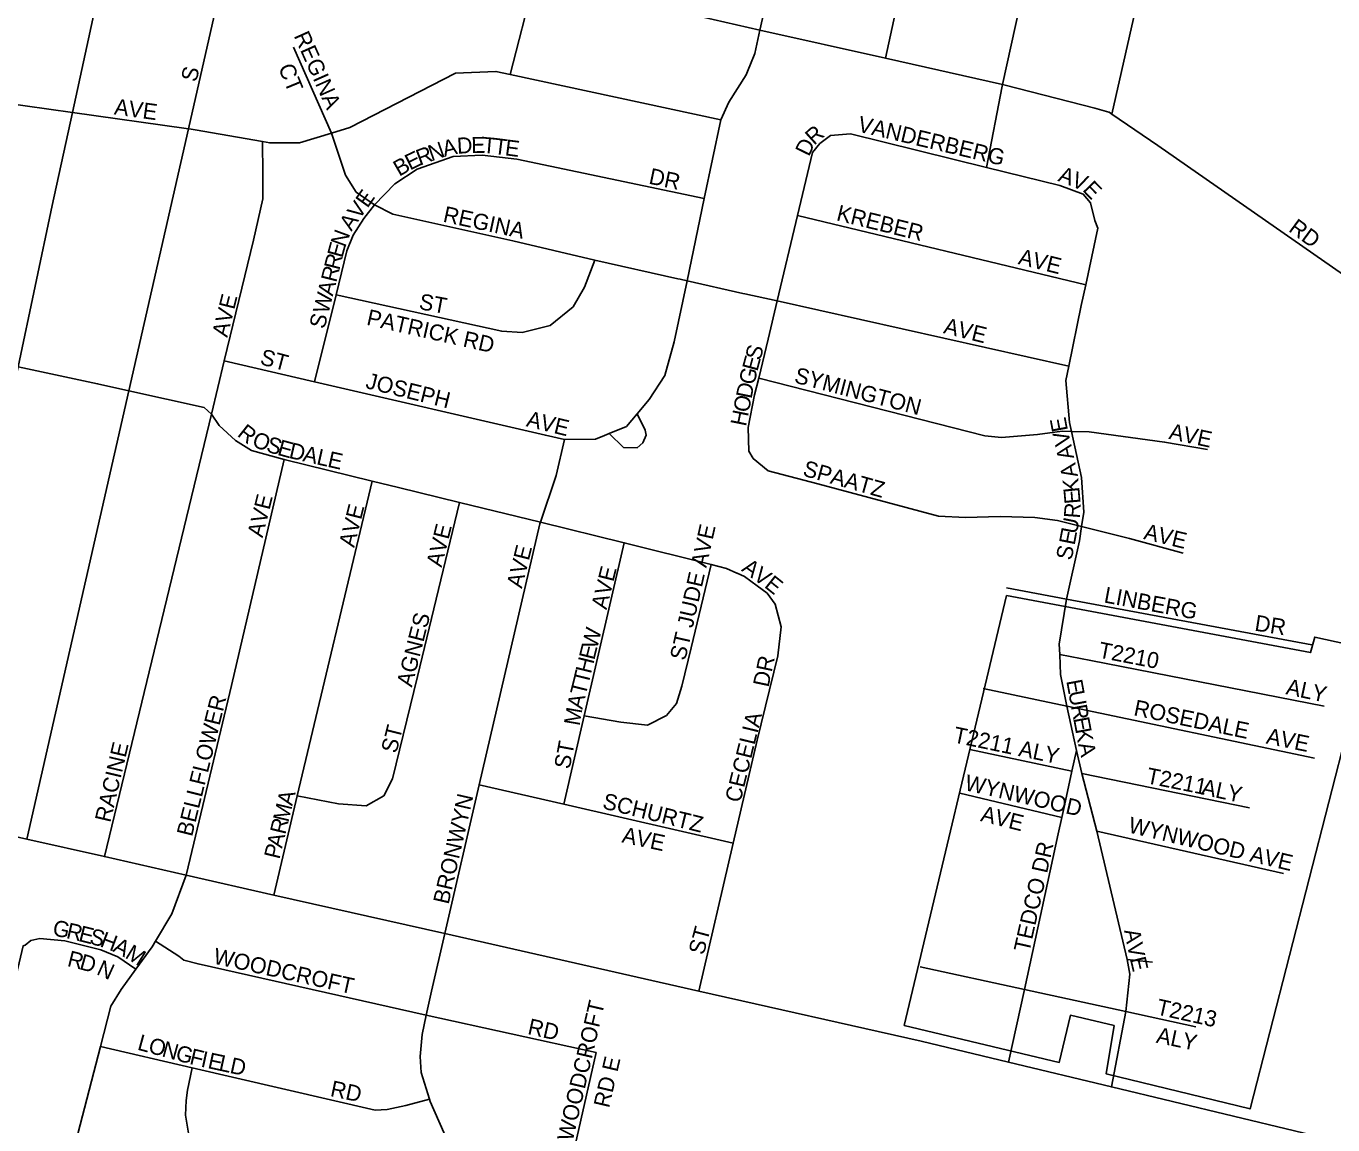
# Model space of a CAD drawing. Extents: x 0 to 34, y -6.2 to 22.
# Drawn here: x 2.696 to 3.469, y 15.73 to 16.379 of the extents above; entities that cross this region are included whole.
import ezdxf

# ---------------------------------------------------------------- set-up
doc = ezdxf.new("R2010")
doc.units = 0
for name, color, linetype in [('GM_X_City_Street', 7, 'Continuous'), ('GM_X_City_Street_Text', 7, 'Continuous'), ('GM_X_Corporation', 7, 'Continuous'), ('GM_X_Township_Subdivision', 7, 'Continuous'), ('GM_X_Township_Subdivision_Text', 7, 'Continuous')]:
    doc.layers.add(name, color=color, linetype=linetype)

msp = doc.modelspace()

# ---------------------------------------------------------------- linework, layer by layer
at = {"layer": 'GM_X_City_Street'}
for points in [[(3.27368, 16.34478), (3.29673, 16.4497), (3.30954, 16.50801), (3.315, 16.53353), (3.31528, 16.53481), (3.32593, 16.58379), (3.32697, 16.59444), (3.32648, 16.60621), (3.3225, 16.6267), (3.32074, 16.63388), (3.29313, 16.7464), (3.25795, 16.89783), (3.24882, 17.00989), (3.23911, 17.16213), (3.23906, 17.16288), (3.23518, 17.3149), (3.22829, 17.42881), (3.22212, 17.56473), (3.2207, 17.60083)], [(3.12582, 16.35982), (3.12602, 16.36031), (3.12718, 16.36323), (3.1303, 16.37705), (3.15398, 16.48197), (3.17382, 16.56986), (3.17844, 16.59036), (3.18149, 16.60756), (3.18168, 16.61593), (3.15792, 16.7142), (3.1215, 16.86577), (3.11952, 16.89635), (3.11304, 17.00234), (3.1055, 17.15726), (3.09863, 17.29851), (3.09286, 17.41697), (3.08623, 17.55807), (3.08431, 17.59258)], [(3.33825, 16.32736), (3.36258, 16.4344), (3.3817, 16.51834), (3.3921, 16.56843), (3.3939, 16.5791), (3.39226, 16.59276), (3.38446, 16.61625), (3.37857, 16.63785), (3.37644, 16.64731), (3.35105, 16.76018), (3.33506, 16.83126), (3.31648, 16.91147), (3.3102, 16.97771), (3.30815, 17.01318), (3.30664, 17.03928), (3.30004, 17.15352), (3.29942, 17.16433), (3.29682, 17.28631)], [(3.20453, 16.36034), (3.22737, 16.4658), (3.24604, 16.55197), (3.25332, 16.58561), (3.25573, 16.60645), (3.25505, 16.61804), (3.25493, 16.62015), (3.22734, 16.73073), (3.19762, 16.84785), (3.18989, 16.88188), (3.1871, 16.92348), (3.18183, 17.00616), (3.17392, 17.15656), (3.17386, 17.15779)], [(2.98264, 16.35074), (2.9967, 16.4053), (2.99695, 16.40657), (2.99976, 16.42157), (3.01237, 16.51308), (3.02837, 16.62912), (3.02846, 16.63274), (3.02872, 16.64356), (3.02719, 16.65842), (3.01097, 16.72809), (2.99061, 16.8133)], [(2.66856, 16.07037), (2.66859, 16.07053), (2.6758, 16.10297), (2.6917, 16.1781), (2.71187, 16.27344), (2.72379, 16.32828), (2.75181, 16.45725), (2.7729, 16.55191)], [(2.82035, 16.4436), (2.82079, 16.44351), (2.82087, 16.4435), (2.87661, 16.43239), (2.90811, 16.42612), (2.93022, 16.42125), (2.99695, 16.40657), (3.05998, 16.39095), (3.09568, 16.38484), (3.1303, 16.37705), (3.20453, 16.36034), (3.27368, 16.34478), (3.27531, 16.34441), (3.32823, 16.33089), (3.33654, 16.32852), (3.33666, 16.32844)], [(2.69685, 15.899), (2.75714, 16.16389), (2.79237, 16.31868), (2.81947, 16.43771), (2.81948, 16.43774)], [(2.87706, 16.31616), (2.85447, 16.36698)], [(2.4876, 16.36137), (2.48773, 16.36135), (2.55231, 16.3523), (2.60686, 16.34467), (2.66762, 16.33615), (2.72379, 16.32828), (2.79099, 16.31887), (2.79237, 16.31868), (2.79396, 16.31845), (2.79646, 16.31802)], [(3.05143, 16.14278), (3.05778, 16.15035), (3.06477, 16.15868), (3.07396, 16.17296), (3.07961, 16.19287), (3.08716, 16.22884), (3.09736, 16.27743), (3.10713, 16.32398), (3.11185, 16.33436), (3.12214, 16.35057), (3.12582, 16.35982)], [(2.79646, 16.31802), (2.83612, 16.31114), (2.84052, 16.31037), (2.85801, 16.31039), (2.87706, 16.31616), (2.88785, 16.31943), (2.95026, 16.35165), (2.97418, 16.35256), (2.98264, 16.35074), (3.10713, 16.32398)], [(3.26422, 16.29587), (3.2735, 16.34382), (3.27368, 16.34478)], [(3.33666, 16.32844), (3.33825, 16.32736), (3.36551, 16.30882), (3.54342, 16.18487), (3.64626, 16.1082), (3.6811, 16.09043), (3.69827, 16.08429), (3.73179, 16.07547), (3.74914, 16.07149), (3.76801, 16.06713)], [(2.74276, 15.8886), (2.80597, 16.15013), (2.81359, 16.18165), (2.83079, 16.25279), (2.83633, 16.27735), (2.8363, 16.29179), (2.83612, 16.31114)], [(2.87706, 16.31616), (2.88529, 16.29135), (2.8915, 16.28132), (2.90234, 16.27384), (2.91322, 16.26825), (2.98424, 16.25245), (3.03258, 16.241), (3.08172, 16.23005), (3.08309, 16.22974)], [(3.12621, 16.12394), (3.12365, 16.12818), (3.12324, 16.14226), (3.12713, 16.16154), (3.12953, 16.17139), (3.13514, 16.19441), (3.14051, 16.21694), (3.15251, 16.26741), (3.16139, 16.30473), (3.16569, 16.30995), (3.17197, 16.31479)], [(3.17197, 16.31479), (3.18374, 16.31581), (3.26422, 16.29587), (3.30761, 16.28512), (3.32141, 16.28011), (3.32571, 16.27487)], [(2.90234, 16.27384), (2.91441, 16.28608), (2.92754, 16.29488), (2.94899, 16.30233), (2.9661, 16.30306), (2.98656, 16.30066), (3.09736, 16.27743)], [(2.86702, 16.16925), (2.87969, 16.22057), (2.88609, 16.24649), (2.88974, 16.2559), (2.89606, 16.26563), (2.90234, 16.27384)], [(3.31161, 16.04084), (3.31913, 16.07513), (3.32048, 16.08368), (3.32182, 16.09217), (3.32042, 16.11272), (3.31442, 16.13985), (3.31323, 16.1452), (3.31118, 16.16995), (3.31293, 16.17851), (3.32024, 16.21419), (3.32289, 16.22651), (3.33009, 16.25994), (3.3283, 16.26454), (3.32571, 16.27487)], [(3.15251, 16.26741), (3.32289, 16.22651)], [(2.87969, 16.22057), (2.97762, 16.19902), (2.98976, 16.19835), (3.00619, 16.2025), (3.01976, 16.21358), (3.0265, 16.22519), (3.03258, 16.241)], [(3.08309, 16.22974), (3.08716, 16.22884), (3.12025, 16.22146), (3.1214, 16.22121)], [(3.1214, 16.22121), (3.14051, 16.21694), (3.31293, 16.17851)], [(2.91659, 16.10674), (2.90096, 16.11057), (2.84905, 16.12329), (2.82966, 16.12854), (2.82031, 16.13447), (2.81065, 16.14345), (2.80597, 16.15013), (2.80179, 16.15393), (2.75714, 16.16389), (2.7387, 16.16801), (2.6917, 16.1781), (2.63443, 16.1904), (2.57441, 16.20328), (2.52273, 16.21438)], [(2.81359, 16.18165), (2.86702, 16.16925), (3.00347, 16.13758), (3.01465, 16.13513), (3.03305, 16.13534), (3.03842, 16.13749), (3.04112, 16.13859), (3.05143, 16.14278)], [(3.12953, 16.17139), (3.26328, 16.1373), (3.27314, 16.1363), (3.29445, 16.13806), (3.30893, 16.13999), (3.31442, 16.13985), (3.32488, 16.1396), (3.36955, 16.13356), (3.39489, 16.12914)], [(3.04112, 16.13859), (3.04964, 16.13038), (3.05761, 16.13018), (3.0611, 16.13313), (3.06311, 16.13765), (3.06243, 16.1407), (3.05778, 16.15035)], [(2.91897, 15.53549), (2.92451, 15.56205), (2.93549, 15.61478), (2.95094, 15.68896), (2.95162, 15.70037), (2.95093, 15.70381), (2.94926, 15.71215), (2.93536, 15.74401), (2.93493, 15.74537), (2.92992, 15.76108), (2.92948, 15.77059), (2.93053, 15.78353), (2.93301, 15.79498), (2.93604, 15.80905), (2.94395, 15.8431), (2.96438, 15.93103), (3.00019, 16.08521), (3.00052, 16.08619), (3.00987, 16.1138), (3.01465, 16.13513)], [(2.727, 15.72474), (2.74044, 15.77646), (2.7466, 15.80018), (2.75261, 15.81011), (2.7614, 15.82214), (2.77104, 15.83534), (2.77298, 15.83858), (2.78268, 15.85481), (2.79097, 15.87768), (2.79125, 15.87845), (2.81781, 15.98968), (2.84905, 16.12329)], [(3.12621, 16.12394), (3.13514, 16.1165), (3.16459, 16.10894), (3.23591, 16.08971), (3.25185, 16.08894), (3.27237, 16.08958), (3.29287, 16.08907), (3.30613, 16.08723), (3.32048, 16.08368), (3.34879, 16.07668), (3.38049, 16.06793)], [(2.84285, 15.86593), (2.85676, 15.92452), (2.90096, 16.11057)], [(3.11678, 16.05611), (3.11671, 16.05615), (3.11058, 16.05895), (3.10153, 16.06128), (3.05002, 16.07407), (3.00052, 16.08619), (2.95264, 16.09791), (2.91659, 16.10674)], [(2.85676, 15.92452), (2.88117, 15.91978), (2.89747, 15.91862), (2.90787, 15.92445), (2.91305, 15.93458), (2.92782, 15.99503), (2.95264, 16.09791)], [(3.01441, 15.91953), (3.02645, 15.97178), (3.05002, 16.07407)], [(3.02645, 15.97178), (3.04796, 15.96814), (3.06387, 15.96623), (3.07503, 15.97204), (3.08089, 15.97912), (3.08419, 15.9893), (3.08967, 16.01196), (3.10153, 16.06128)], [(3.1393, 16.03773), (3.13452, 16.04431), (3.12855, 16.04863), (3.12109, 16.05414), (3.11678, 16.05611)], [(3.1393, 16.03773), (3.14277, 16.02434), (3.14084, 16.00729), (3.12861, 15.95743), (3.11445, 15.89654), (3.09413, 15.80919)], [(2.27548, 16.00583), (2.39781, 15.96666), (2.51402, 15.94006), (2.57435, 15.92657), (2.63369, 15.91331), (2.69685, 15.899), (2.74276, 15.8886), (2.79097, 15.87768), (2.84285, 15.86593), (2.94395, 15.8431), (3.09413, 15.80919), (3.22563, 15.77956), (3.27728, 15.76715), (3.33809, 15.75253), (3.48234, 15.71786), (3.52432, 15.70777), (3.6965, 15.66649)], [(2.96438, 15.93103), (3.01441, 15.91953), (3.11445, 15.89654)], [(2.66196, 15.69809), (2.6947, 15.83597), (2.69584, 15.83636), (2.69924, 15.83904)], [(2.69924, 15.83904), (2.70455, 15.84022), (2.71937, 15.8388), (2.74067, 15.83361), (2.75058, 15.8295), (2.7614, 15.82214)], [(2.77298, 15.83858), (2.78665, 15.82973), (2.78971, 15.82747), (2.79808, 15.82525), (2.93301, 15.79498), (3.03352, 15.7728)], [(2.74044, 15.77646), (2.79468, 15.76388), (2.90274, 15.73884), (2.90995, 15.73927), (2.92095, 15.74163), (2.93493, 15.74537)], [(3.01539, 15.69288), (3.03352, 15.7728)], [(2.88387, 15.62694), (2.89367, 15.67717), (2.89365, 15.68135), (2.89249, 15.68439), (2.88943, 15.68741), (2.87383, 15.69073), (2.81982, 15.7033), (2.81221, 15.70554), (2.8065, 15.70778), (2.80115, 15.71269), (2.79733, 15.71495), (2.79271, 15.72404), (2.79072, 15.73582), (2.79104, 15.74457), (2.79176, 15.75066), (2.79468, 15.76388)]]:
    msp.add_lwpolyline(points, dxfattribs=at)
at = {"layer": 'GM_X_Corporation'}
msp.add_lwpolyline([(3.27614, 16.04285), (3.4558, 16.00921), (3.45825, 16.01836), (3.48981, 16.01134), (3.42002, 15.73959), (3.33493, 15.76028), (3.33963, 15.78876), (3.31384, 15.7949), (3.30722, 15.76707), (3.21557, 15.78887), (3.27614, 16.04285)], dxfattribs=at)
at = {"layer": 'GM_X_Township_Subdivision'}
for points in [[(3.27603, 16.04748), (3.31161, 16.04084), (3.45647, 16.01379)], [(3.33809, 15.75253), (3.34667, 15.7971), (3.34906, 15.81921), (3.3474, 15.82786), (3.32943, 15.90369), (3.32068, 15.93774), (3.31735, 15.9513), (3.31167, 15.97756), (3.3079, 15.9963), (3.30749, 16.00802), (3.30728, 16.01417), (3.31161, 16.04084)], [(3.30749, 16.00802), (3.32588, 16.00444)], [(3.32588, 16.00444), (3.32588, 16.00444), (3.46378, 15.97762)], [(3.26228, 15.9879), (3.31167, 15.97756), (3.45823, 15.94687)], [(3.31471, 15.93918), (3.25442, 15.95184)], [(3.30666, 15.90218), (3.30875, 15.91182), (3.31028, 15.9188), (3.31471, 15.93918), (3.31735, 15.9513)], [(3.41966, 15.91751), (3.32068, 15.93774)], [(3.24852, 15.92604), (3.30875, 15.91182)], [(3.27728, 15.76715), (3.28664, 15.81016), (3.30666, 15.90218)], [(3.32943, 15.90369), (3.43986, 15.87858)], [(3.22496, 15.82358), (3.28664, 15.81016), (3.34667, 15.7971), (3.38792, 15.78812)], [(3.3474, 15.82786), (3.3624, 15.82633)]]:
    msp.add_lwpolyline(points, dxfattribs=at)

# ---------------------------------------------------------------- texts
at = {"layer": 'GM_X_City_Street_Text'}
for s, height, rotation, p in [('REGINA', 0.00947, 294.07674, (2.85454, 16.37368)), ('S', 0.00947, 75.97018, (2.79702, 16.34589)), ('CT', 0.00947, 292.38208, (2.84533, 16.35493)), ('AVE', 0.00947, 352.15077, (2.74816, 16.32722)), ('VANDERBERG', 0.00947, 346.69152, (3.18749, 16.31719)), ('R', 0.00947, 42.04497, (3.16231, 16.30858)), ('N', 0.00947, 19.45094, (2.93611, 16.29942)), ('A', 0.00947, 12.98151, (2.94369, 16.30211)), ('D', 0.00947, 3.08285, (2.95139, 16.30393)), ('E', 0.00947, 0.87426, (2.95962, 16.30437)), ('T', 0.00947, 354.96635, (2.96602, 16.30448)), ('T', 0.00947, 352.87837, (2.97257, 16.30391)), ('E', 0.00947, 352.71231, (2.97918, 16.30308)), ('D', 0.00947, 63.88454, (3.15921, 16.30185)), ('B', 0.00947, 29.95575, (2.91702, 16.29029)), ('E', 0.00947, 26.13748, (2.92337, 16.29396)), ('R', 0.00947, 20.60153, (2.92914, 16.2968)), ('DR', 0.00947, 348.1183, (3.06411, 16.28633)), ('A', 0.00947, 339.27002, (3.30601, 16.28797)), ('V', 0.00947, 336.67226, (3.3137, 16.28506)), ('E', 0.00947, 314.3237, (3.32055, 16.28231)), ('E', 0.00947, 54.45278, (2.89819, 16.27141)), ('V', 0.00947, 54.45469, (2.89335, 16.26463)), ('REGINA', 0.00947, 347.83063, (2.94246, 16.26386)), ('KREBER', 0.00947, 346.22215, (3.175, 16.26468)), ('A', 0.00947, 56.15231, (2.88875, 16.25777)), ('RD', 0.00947, 323.75059, (3.44228, 16.25853)), ('N', 0.00947, 69.98888, (2.88509, 16.24823)), ('E', 0.00947, 74.82395, (2.88341, 16.24199)), ('AVE', 0.00947, 345.96376, (3.28251, 16.23885)), ('R', 0.00947, 75.88648, (2.88159, 16.23476)), ('R', 0.00947, 75.86951, (2.87976, 16.22749)), ('A', 0.00947, 75.86832, (2.87772, 16.21941)), ('AVE', 0.00947, 75.96375, (2.81535, 16.19505)), ('W', 0.00947, 75.86996, (2.87508, 16.2089)), ('ST', 0.00947, 349.38777, (2.92824, 16.2122)), ('S', 0.00947, 75.87099, (2.87284, 16.20001)), ('PATRICK RD', 0.00947, 347.32085, (2.89723, 16.20296)), ('AVE', 0.00947, 345.96376, (3.23834, 16.19802)), ('ST', 0.00947, 345.06224, (2.8342, 16.17967)), ('S', 0.00947, 74.76405, (3.13048, 16.18137)), ('E', 0.00947, 74.85032, (3.12874, 16.17494)), ('SYMINGTON', 0.00947, 345.29141, (3.15003, 16.16884)), ('JOSEPH', 0.00947, 346.20039, (2.89667, 16.16552)), ('G', 0.00947, 77.06107, (3.1269, 16.16691)), ('D', 0.00947, 78.66868, (3.12528, 16.15881)), ('O', 0.00947, 78.64719, (3.12363, 16.15063)), ('A', 0.00947, 346.00616, (2.99168, 16.14301)), ('V', 0.00947, 345.97966, (2.99977, 16.141)), ('E', 0.00947, 346.40562, (3.00792, 16.13896)), ('H', 0.00947, 78.66863, (3.122, 16.14247)), ('E', 0.00947, 100.4686, (3.31242, 16.14053)), ('R', 0.00947, 321.52224, (2.82076, 16.13754)), ('O', 0.00947, 339.52073, (2.82944, 16.13128)), ('V', 0.00947, 103.09201, (3.31428, 16.13253)), ('AVE', 0.00947, 347.90418, (3.37162, 16.13553)), ('S', 0.00947, 342.95236, (2.83784, 16.12816)), ('E', 0.00947, 344.57704, (2.84449, 16.12612)), ('D', 0.00947, 346.98623, (2.85134, 16.12425)), ('A', 0.00947, 102.44222, (3.3161, 16.12427)), ('A', 0.00947, 347.33061, (2.85952, 16.12235)), ('L', 0.00947, 347.32895, (2.86765, 16.12052)), ('E', 0.00947, 347.32895, (2.87416, 16.11906)), ('SPAATZ', 0.00947, 344.35759, (3.15506, 16.11383)), ('A', 0.00947, 101.3418, (3.31832, 16.11347)), ('K', 0.00947, 95.7887, (3.31931, 16.10419)), ('AVE', 0.00947, 75.96375, (2.83618, 16.07672)), ('E', 0.00947, 94.94436, (3.3199, 16.0974)), ('AVE', 0.00947, 75.96375, (2.89035, 16.07089)), ('R', 0.00947, 85.70031, (3.31934, 16.08825)), ('AVE', 0.00947, 75.96375, (2.94202, 16.05922)), ('ST JUDE AVE', 0.0094697, 77.25491, (3.08615, 16.00408)), ('U', 0.00947, 78.82721, (3.31756, 16.07884)), ('AVE', 0.00947, 346.43104, (3.35666, 16.07635)), ('E', 0.00947, 78.83476, (3.31627, 16.0723)), ('AVE', 0.00947, 75.96375, (2.98952, 16.04672)), ('S', 0.00947, 78.83476, (3.3145, 16.06331)), ('A', 0.00947, 324.48519, (3.1189, 16.05777)), ('AVE', 0.00947, 75.96375, (3.03952, 16.03422)), ('V', 0.00947, 324.51071, (3.12568, 16.05293)), ('E', 0.00947, 321.21222, (3.13235, 16.04818)), ('AGNES', 0.00947, 75.71822, (2.92451, 15.98838)), ('W', 0.00947, 76.1923, (3.03394, 16.01087)), ('E', 0.00947, 76.17584, (3.03235, 16.0044)), ('H', 0.00947, 76.18636, (3.03036, 15.99631)), ('DR', 0.00947, 78.11829, (3.13534, 15.98832)), ('T', 0.00947, 76.17584, (3.02717, 15.98336)), ('T', 0.00947, 76.19191, (3.02877, 15.98983)), ('BELLFLOWER', 0.00947, 76.11525, (2.79452, 15.90005)), ('M', 0.00947, 80.33704, (3.02363, 15.96556)), ('A', 0.00947, 76.79076, (3.02527, 15.97527)), ('CECELIA', 0.00947, 76.20038, (3.11868, 15.92005)), ('ST', 0.00947, 75.97018, (2.91535, 15.94922)), ('RACINE', 0.00947, 76.75804, (2.74618, 15.90836)), ('ST', 0.00947, 79.37209, (3.01783, 15.93995)), ('A', 0.00947, 75.68809, (2.85376, 15.91826)), ('BRONWYN', 0.00947, 77.12584, (2.94618, 15.86002)), ('SCHURTZ', 0.00947, 346.1857, (3.03667, 15.91719)), ('M', 0.00947, 76.49815, (2.85144, 15.90857)), ('R', 0.00947, 76.48825, (2.84968, 15.90128)), ('A', 0.00947, 76.4917, (2.84774, 15.89318)), ('AVE', 0.00947, 347.90418, (3.04821, 15.8971)), ('P', 0.00947, 76.48726, (2.84618, 15.8867)), ('G', 0.00947, 348.33425, (2.71158, 15.8422)), ('R', 0.00947, 346.97081, (2.71968, 15.84053)), ('E', 0.00947, 345.98363, (2.72695, 15.83885)), ('S', 0.00947, 345.81134, (2.73341, 15.83724)), ('ST', 0.00947, 75.06586, (3.09702, 15.83008)), ('H', 0.00947, 339.35953, (2.7396, 15.83569)), ('A', 0.00947, 332.68226, (2.74714, 15.83287)), ('R', 0.00947, 345.89307, (2.72027, 15.82405)), ('D', 0.00947, 344.35186, (2.72747, 15.82224)), ('M', 0.00947, 328.50826, (2.75438, 15.82913)), ('WOODCROFT', 0.00947, 347.54387, (2.80663, 15.82552)), ('N', 0.00947, 335.59585, (2.7375, 15.81931)), ('WOODCROFT', 0.00947, 76.91057, (3.01951, 15.72002)), ('RD', 0.00947, 347.47634, (2.99247, 15.78386)), ('L', 0.00947, 344.65141, (2.76172, 15.77467)), ('O', 0.00947, 344.62797, (2.76815, 15.77291)), ('N', 0.00947, 344.63188, (2.77619, 15.7707)), ('G', 0.00947, 344.70283, (2.78423, 15.76849)), ('F', 0.00947, 346.45318, (2.79258, 15.76621)), ('I', 0.00947, 347.67025, (2.79927, 15.7646)), ('E', 0.00947, 347.80702, (2.80337, 15.76371)), ('L', 0.00947, 347.80603, (2.80989, 15.7623)), ('D', 0.00947, 347.79838, (2.8164, 15.76089)), ('RD E', 0.00947, 76.86551, (3.04104, 15.7397)), ('RD', 0.00947, 348.10728, (2.87578, 15.74719))]:
    msp.add_text(s, height=height, rotation=rotation, dxfattribs=at).set_placement(p)
at = {"layer": 'GM_X_Township_Subdivision_Text'}
for s, height, rotation, p in [('LINBERG', 0.00947, 349.44142, (3.33324, 16.03887)), ('DR', 0.00947, 351.03269, (3.42236, 16.02221)), ('T2210', 0.00947, 348.9963, (3.32992, 16.00634)), ('E', 0.00947, 280.54919, (3.31134, 15.99244)), ('ALY', 0.00947, 347.90418, (3.44078, 15.98467)), ('U', 0.00947, 280.52969, (3.31256, 15.98589)), ('R', 0.00947, 280.5242, (3.31408, 15.97769)), ('ROSEDALE', 0.00947, 348.23256, (3.35077, 15.9722)), ('E', 0.00947, 280.56116, (3.31545, 15.97031)), ('T2211 ALY', 0.00947, 348.19785, (3.24409, 15.95625)), ('K', 0.00947, 280.55542, (3.31667, 15.96376)), ('AVE', 0.00947, 348.30939, (3.42911, 15.95553)), ('A', 0.00947, 283.1493, (3.31829, 15.95511)), ('T2211', 0.00947, 348.69007, (3.35824, 15.93208)), ('WYNWOOD', 0.00947, 347.06342, (3.25081, 15.92802)), ('ALY', 0.00947, 347.90418, (3.39076, 15.92542)), ('AVE', 0.00947, 345.96376, (3.26023, 15.90971)), ('WYNWOOD AVE', 0.0094697, 346.60666, (3.34749, 15.90302)), ('TEDCO DR', 0.00947, 77.38071, (3.28951, 15.83168)), ('A', 0.00947, 281.50709, (3.3455, 15.84496)), ('V', 0.00947, 281.51391, (3.34716, 15.8368)), ('E', 0.00947, 283.52782, (3.3489, 15.82827)), ('T2213', 0.00947, 347.47184, (3.36413, 15.7955)), ('ALY', 0.00947, 348.30939, (3.36414, 15.77875))]:
    msp.add_text(s, height=height, rotation=rotation, dxfattribs=at).set_placement(p)

doc.saveas('drawing.dxf')
